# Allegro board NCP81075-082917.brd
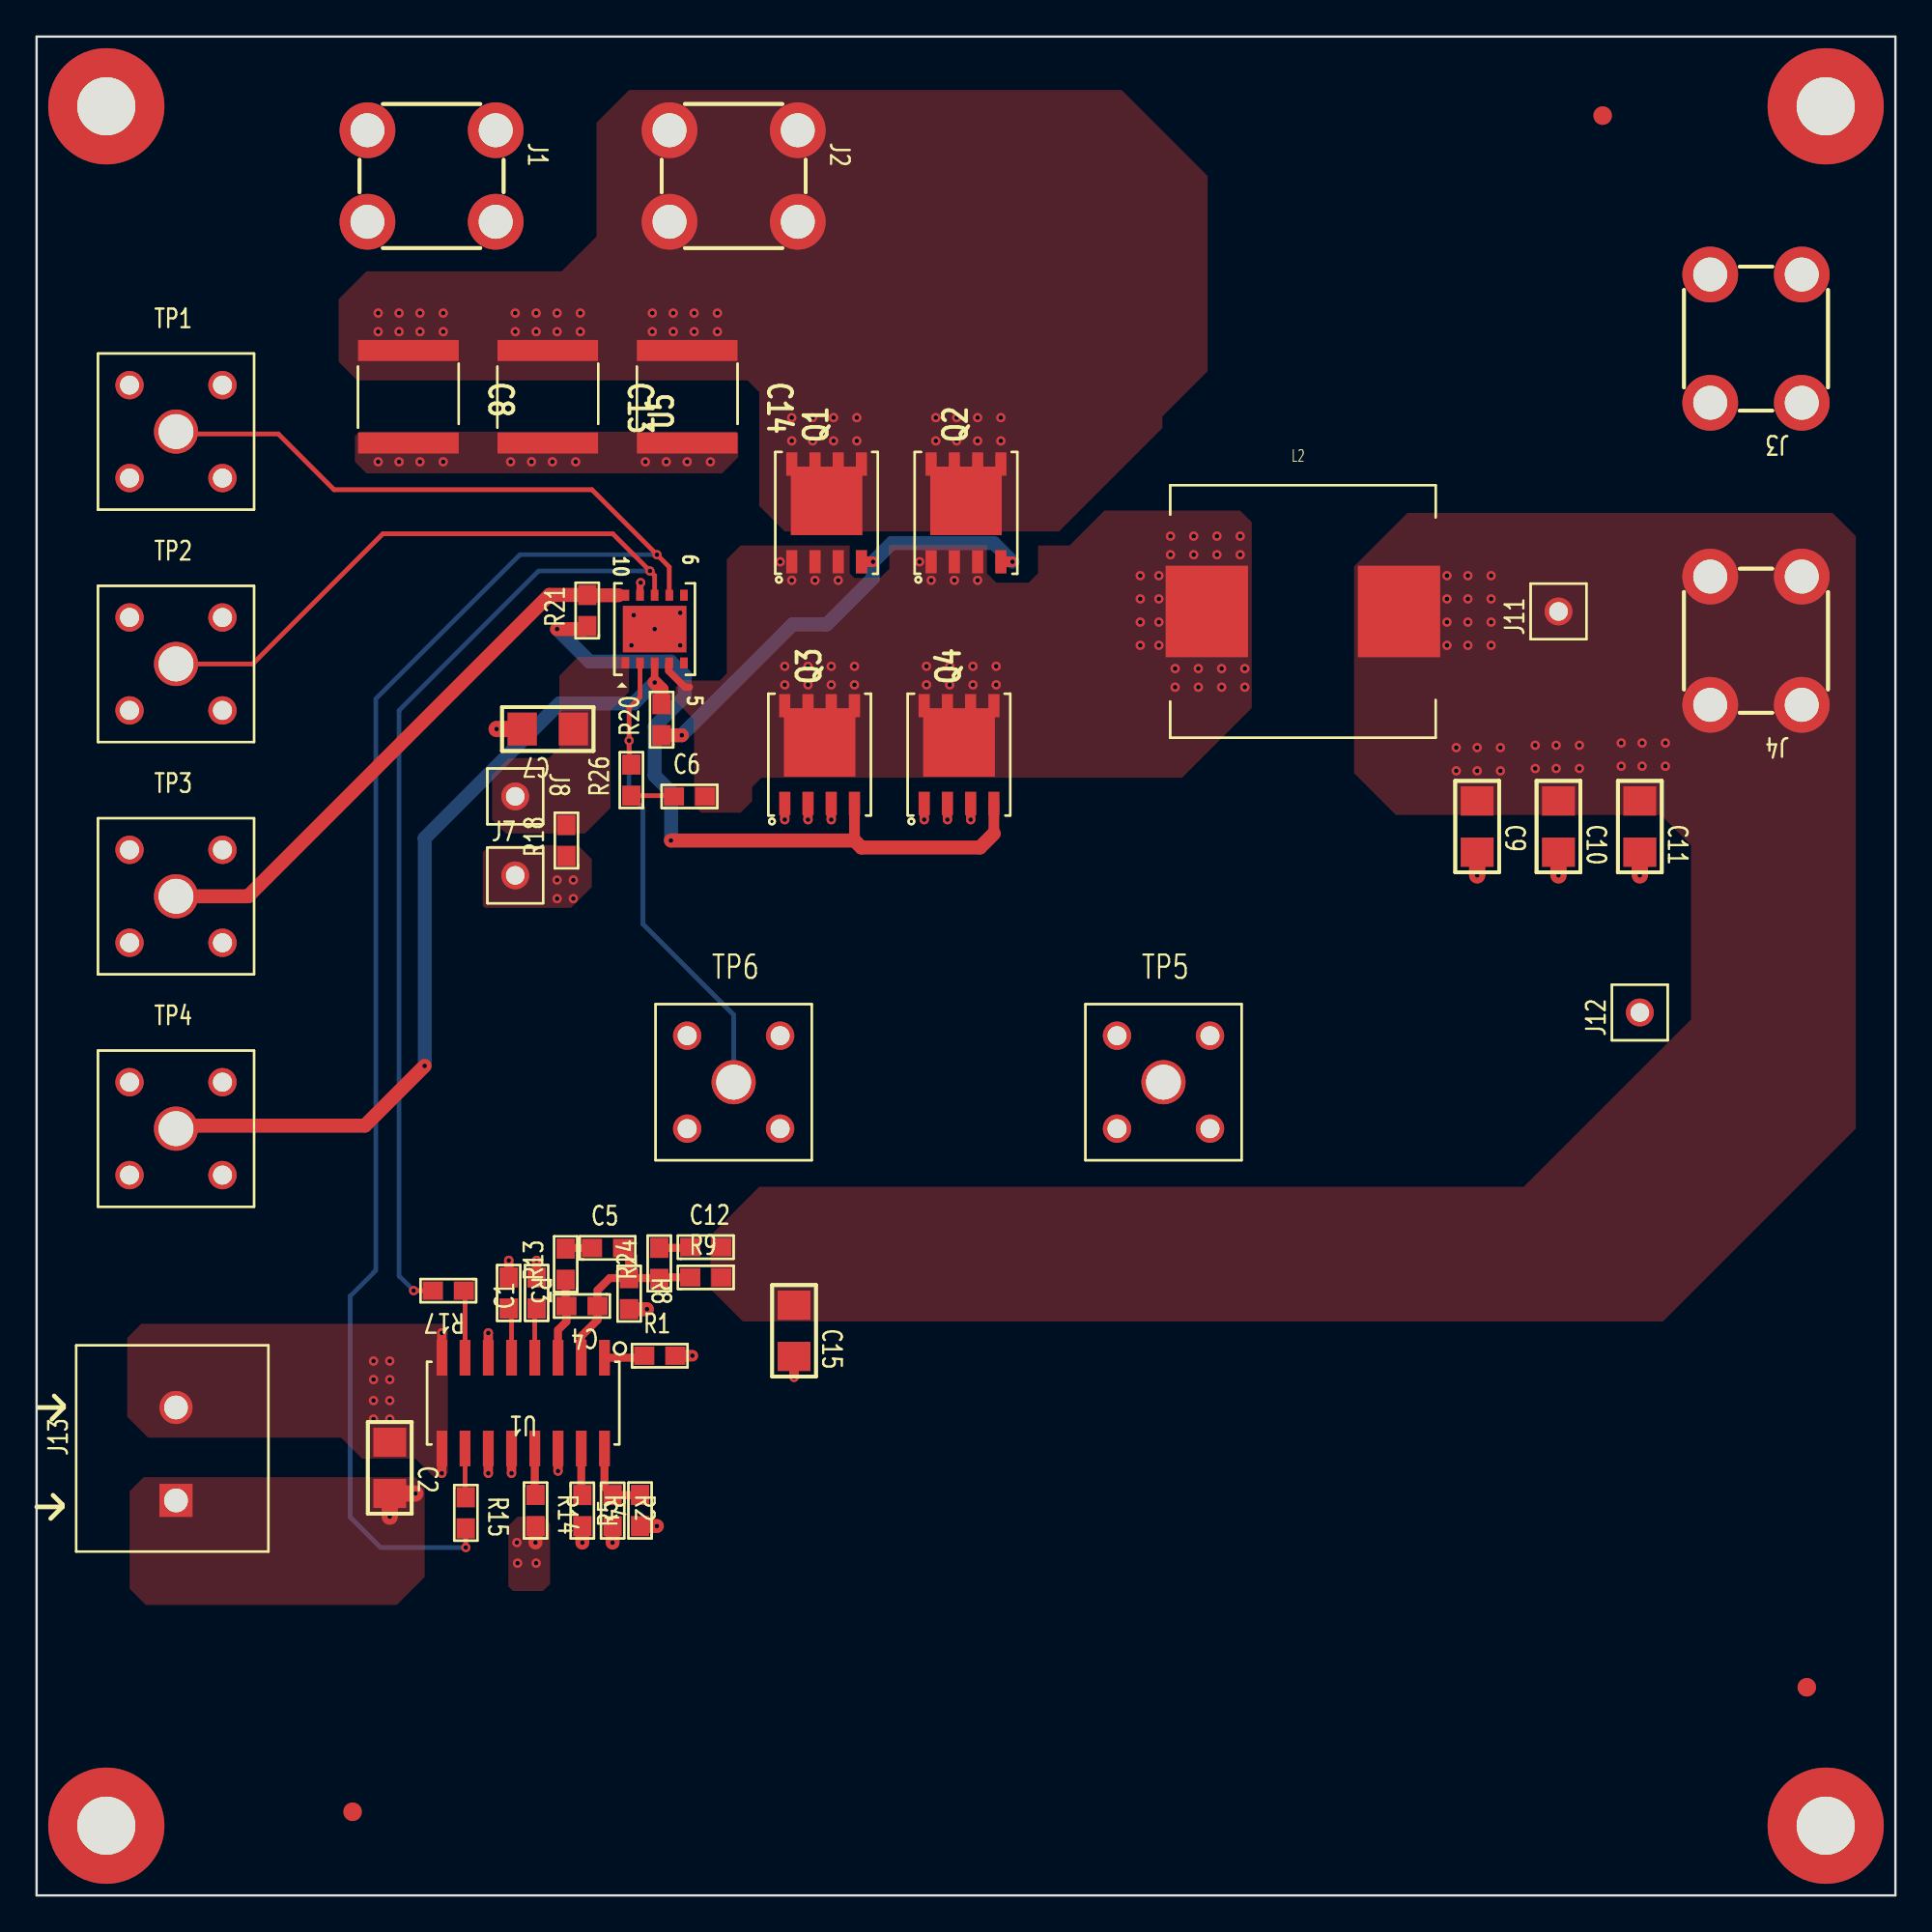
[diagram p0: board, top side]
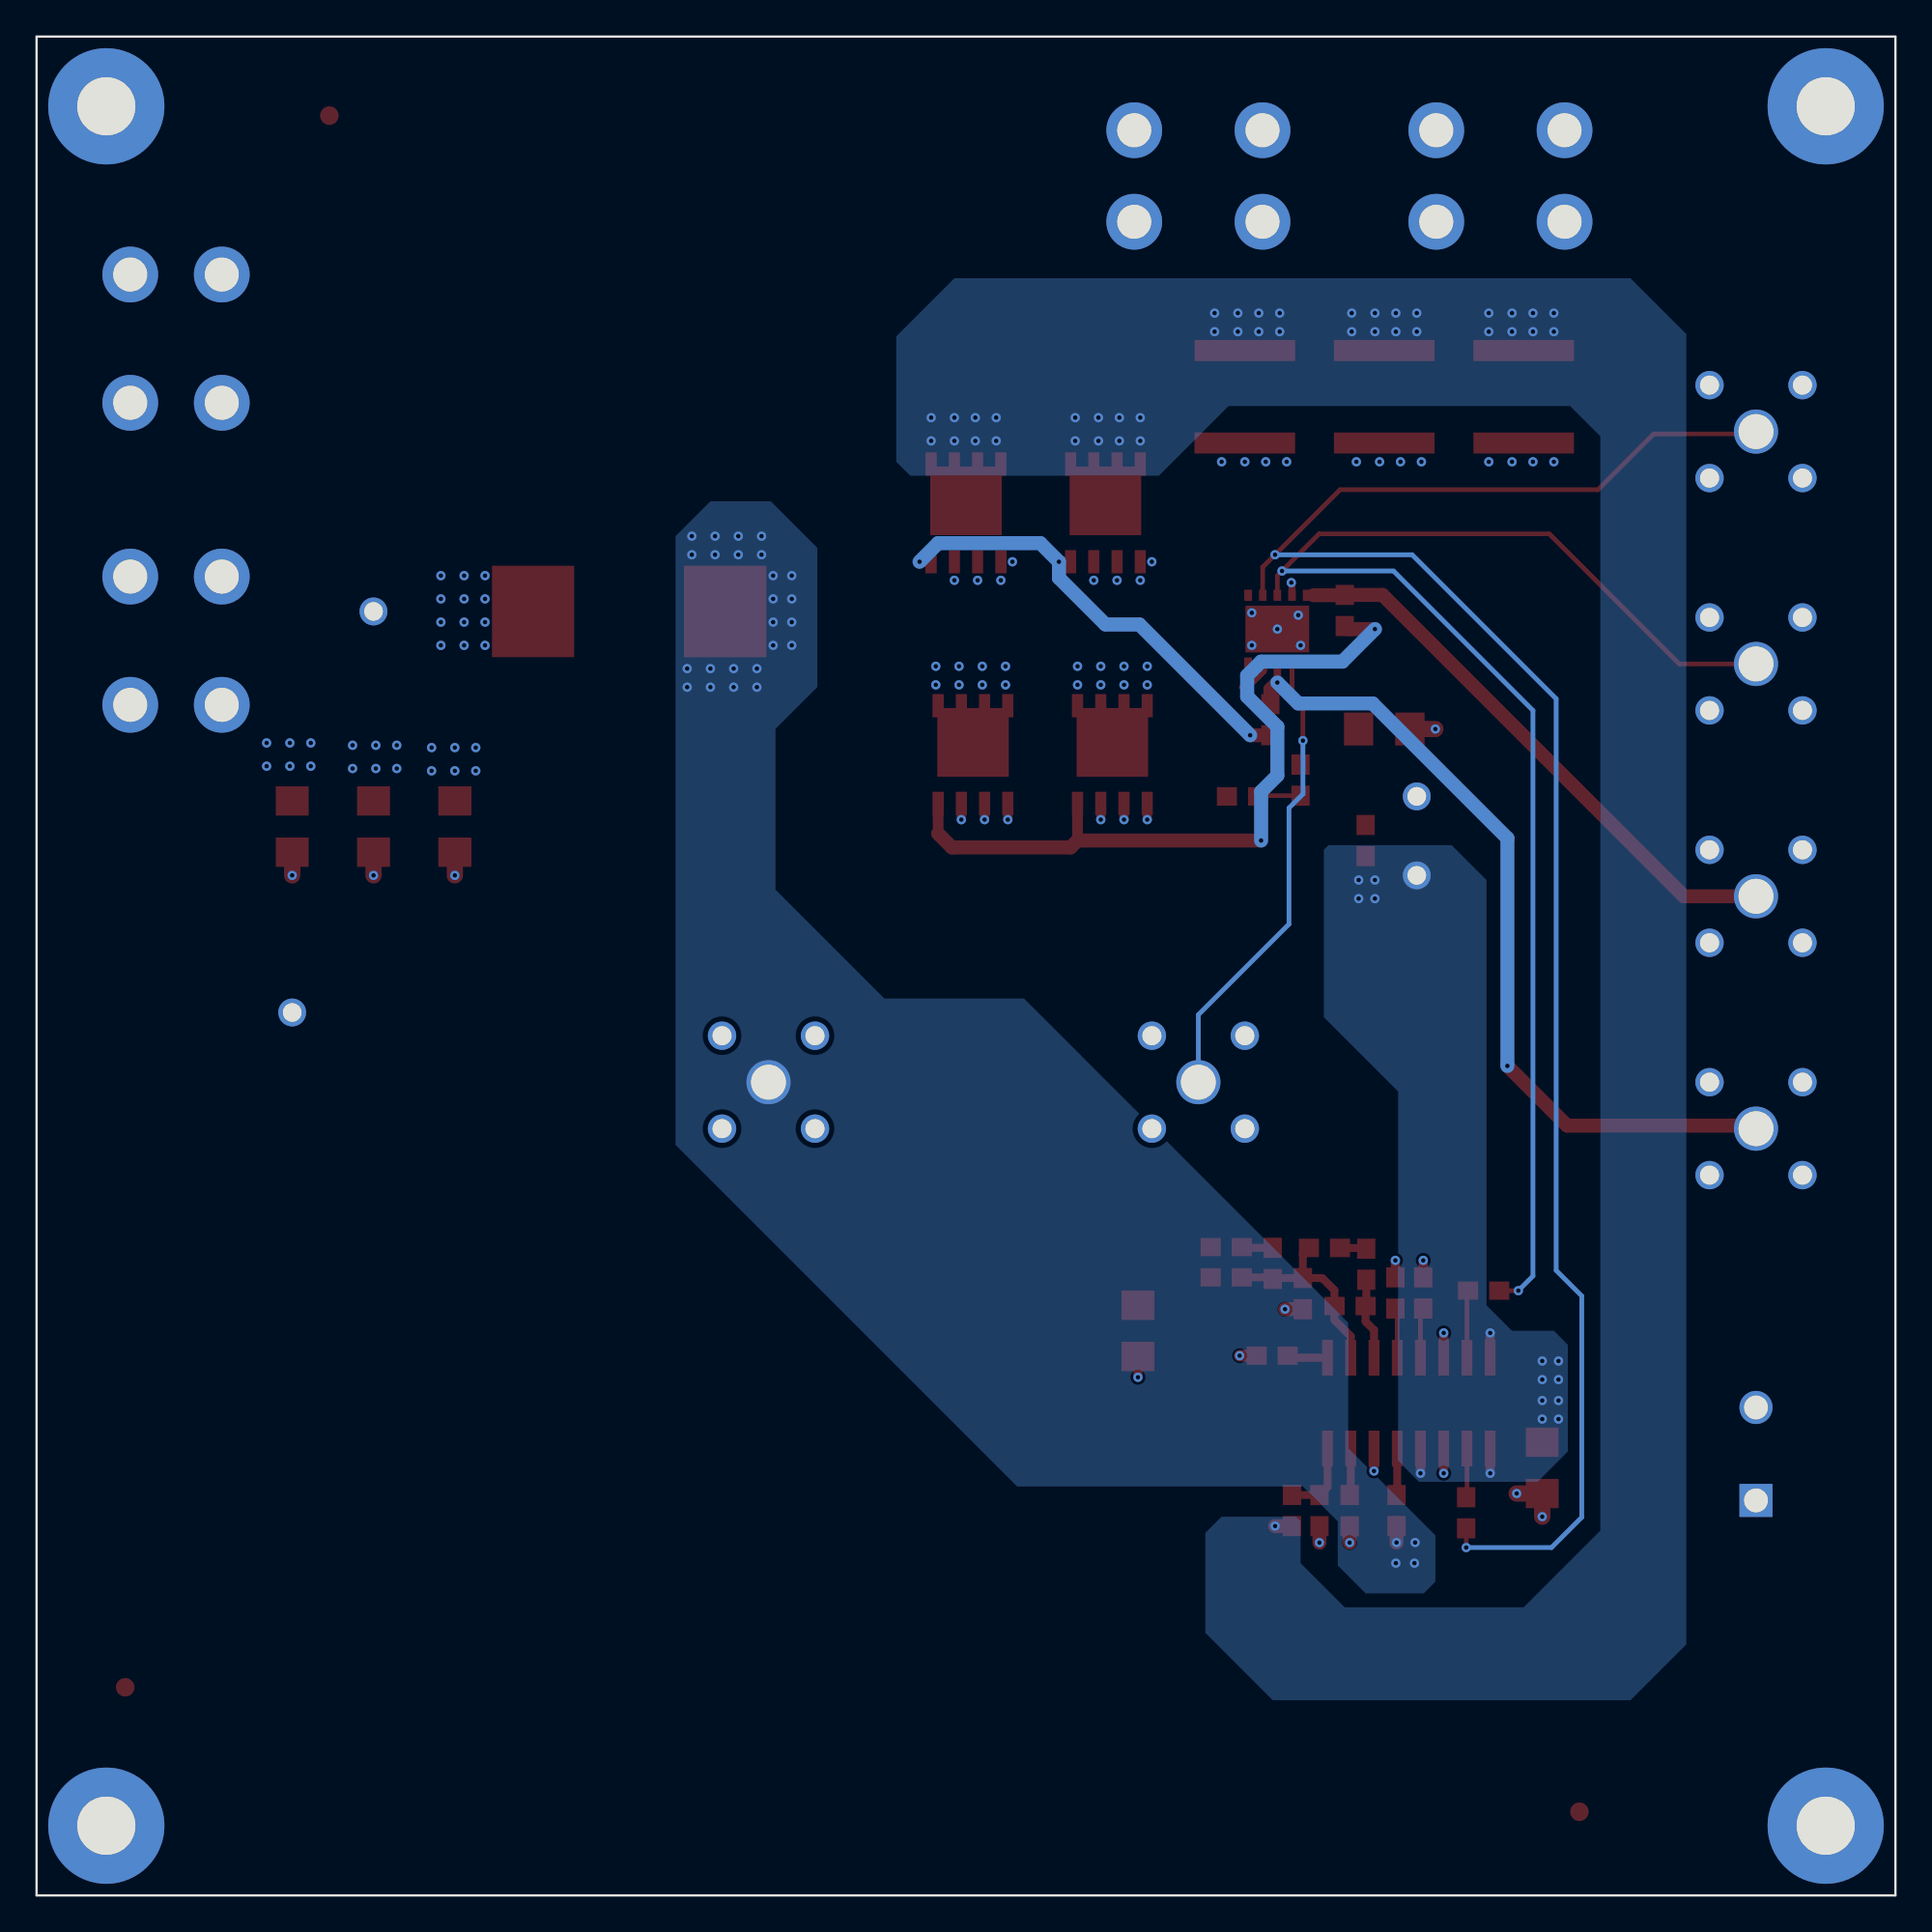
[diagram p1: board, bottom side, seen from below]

Outline 101.6 x 101.6 mm; copper layers: TOP, GND1#2, GND2#3, BOTTOM. Coordinates in mm from the lower left corner of the outline.
Outline path: 0,101.6 0,0 101.6,0 101.6,101.6 0,101.6

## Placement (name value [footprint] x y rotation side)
C1  220nF  [0603]  27.33 32.93 90 top
C2  4.7uF  [SMD1206]  19.3 23.37 270 top
C4  330pF  [0603]  29.81 32.21 180 top
C5  12nF  [0603]  31.21 35.39 0 top
C6  100nF  [0603]  35.69 60.07 0 top
C7  4.7uF  [SMD1206]  27.94 63.75 180 top
C8  10uF  [SMD2220]  20.32 81.92 270 top
C9  47uF  [SMD1206]  78.74 58.42 270 top
C10  47uF  [SMD1206]  83.19 58.42 270 top
C11  47uF  [SMD1206]  87.63 58.42 270 top
C12  1.8nF  [0603]  36.58 35.43 0 top
C13  10uF  [SMD2220]  27.94 81.92 270 top
C14  10uF  [SMD2220]  35.56 81.92 270 top
C15  47uF  [SMD1206]  41.4 30.86 270 top
J1  4PIN  [TRM4]  21.59 93.98 270 top
J2  4PIN  [TRM4]  38.1 93.98 270 top
J3  4PIN  [TRM4]  93.98 85.09 180 top
J4  4PIN  [TRM4]  93.98 68.58 180 top
J7  TP  [TRM1]  26.16 55.75 0 top
J8  TP  [TRM1]  26.16 60.07 270 top
J11  TP  [TRM1]  83.19 70.18 90 top
J12  TP  [TRM1]  87.63 48.26 90 top
J13  2PIN/TERM BLK  [TRM2]  7.62 24.13 90 top
L2  7443551181  [INDUCTOR]  69.22 70.18 0 top
NOREF  -  [unnamed]  3.81 3.81 0 top
NOREF#2  -  [unnamed]  96.76 11.38 0 top
NOREF#3  -  [#2]  0 0 0 top
NOREF#4  -  [unnamed]  97.79 3.81 0 top
NOREF#5  -  [#2]  0 0 0 top
NOREF#6  -  [unnamed]  85.6 97.28 0 top
NOREF#7  -  [#2]  3.81 97.79 0 top
NOREF#8  -  [unnamed]  3.81 97.79 0 top
NOREF#9  -  [unnamed]  17.27 4.57 0 top
NOREF#10  -  [#2]  101.6 0.13 90 top
NOREF#11  -  [#2]  0 101.6 0 top
NOREF#12  -  [unnamed]  97.79 97.79 0 top
Q1  FDMS86102LZ  [PQFN-8]  43.18 75.56 90 top
Q2  FDMS86102LZ  [PQFN-8]  50.8 75.56 90 top
Q3  FDMS86102LZ  [PQFN-8]  42.8 62.36 90 top
Q4  FDMS86102LZ  [PQFN-8]  50.42 62.36 90 top
R1  10K  [0603]  34.06 29.5 0 top
R2  DNP  [0603]  31.48 21.03 270 top
R3  10K  [0603]  25.81 32.93 270 top
R4  20K  [0603]  29.83 21.03 270 top
R5  100K  [0603]  32.98 21.04 90 top
R8  5.6k  [0603]  32.38 32.89 270 top
R9  16.9k  [0603]  36.58 33.78 0 top
R13  4.7K  [0603]  28.92 34.5 90 top
R14  10K  [0603]  27.27 21.04 270 top
R15  0  [0603]  23.46 20.91 270 top
R17  0  [0603]  22.5 33.06 180 top
R18  1  [0603]  28.96 57.66 90 top
R20  2.2  [0603]  34.16 64.26 90 top
R21  2.2  [0603]  30.1 70.23 90 top
R24  1.2K  [0603]  34.04 34.54 90 top
R26  2.2  [0603]  32.51 60.96 90 top
TP1  Probe Ground Tip  [SMA]  7.62 80.01 0 top
TP2  Probe Ground Tip  [SMA]  7.62 67.31 0 top
TP3  Probe Ground Tip  [SMA]  7.62 54.61 0 top
TP4  Probe Ground Tip  [SMA]  7.62 41.91 0 top
TP5  Probe Ground Tip  [SMA]  61.59 44.45 0 top
TP6  Probe Ground Tip  [SMA]  38.1 44.45 0 top
U1  NCP1034  [SOIC-16]  26.59 26.91 180 top
U5  NCP81075  [DFN8]  33.78 69.22 90 top
UNK*  -  [#2]  32 -36.07 0 top

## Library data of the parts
C1 = CAP_9
C2 = CAP_4
C4 = CAP_6
C5 C12 = CAP_7
C6 = CAP_11
C7 = CAP_10
C8 C13 C14 = CAP_12
C9 C11 C15 = CAP_14
C10 = CAP_15
J1 = Power_term_0
J2-J4 = Power_term
J7 J8 J11 J12 = TP_SQUARE
J13 = Term_Blk_2_0.2
L2 = INDUCTOR_0
Q1-Q4 = MTD10N05E_0
R1 = RES_19
R2 = RES_15
R3 = RES_17
R4 = RES_18
R5 = RES_14
R8 = RES_11
R9 R24 = RES_10
R13 = RES_12
R14 = RES_6
R15 = RES_20
R17 = RES_5
R18 = RES_13
R20 R21 R26 = RES_9
TP1-TP6 = BNC_0
U1 = COP245C_0
U5 = ADP3418_3

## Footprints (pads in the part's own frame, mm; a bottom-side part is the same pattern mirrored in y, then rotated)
0603
  rect 1.1x1 smd: 1(-0.85,0) 2(0.85,0)
DFN8
  rect 0.6x0.42 smd: 1(-1.85,1.6) 2(-1.85,0.8) 3(-1.85,0) 4(-1.85,-0.8) 5(-1.85,-1.6) 6(1.85,-1.6) 7(1.85,-0.8) 8(1.85,0) 9(1.85,0.8) 10(1.85,1.6)
  rect 2.55x3.48 smd: TAB(0,0)
INDUCTOR
  rect 4.5x5 smd: 1(-5.25,0) 2(5.25,0)
PQFN-8
  rect 1.27x0.61 smd: 1(-2.67,1.905) 2(-2.67,0.635) 3(-2.67,-0.635) 4(-2.67,-1.905)
  custom 1.105x1.105 smd: 5(1.045,0)
SMA
  round 2.413 hole 1.905: 1(0,0)
  round 1.549 hole 1.041: 2(2.54,-2.54) 3(2.54,2.54) 4(-2.54,2.54) 5(-2.54,-2.54)
SMD1206
  rect 1.6x1.8 smd: 1(-1.4,0) 2(1.4,0)
SMD2220
  rect 1.15x5.5 smd: 1(-2.53,0) 2(2.53,0)
SOIC-16
  rect 0.59x1.95 smd: 1(-4.445,-2.48) 2(-3.175,-2.48) 3(-1.905,-2.48) 4(-0.635,-2.48) 5(0.635,-2.48) 6(1.905,-2.48) 7(3.175,-2.48) 8(4.445,-2.48) 9(4.445,2.48) 10(3.175,2.48) 11(1.905,2.48) 12(0.635,2.48) 13(-0.635,2.48) 14(-1.905,2.48) 15(-3.175,2.48) 16(-4.445,2.48)
TRM1
  round 1.524 hole 1.016: 1(0,0)
TRM2
  rect 1.808x1.808 hole 1.3: 1(-2.54,0)
  round 1.808 hole 1.3: 2(2.54,0)
TRM4
  round 3.048 hole 1.854: 1(-2.502,3.505) 2(2.502,3.505) 3(-2.502,-3.505) 4(2.502,-3.505)
unnamed
  round 6.35 hole 3.175 unplated: (0,0)

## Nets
12V: C2.1 J7.1 J13.2 R18.1 U1.8(DRVVCC) U1.9(VB) U1.12(VCC)
GND: C1.2 C2.2 C7.2 C8.2 C9.2 C10.2 C11.2 C13.2 C14.2 C15.2 J1.1 J1.2 J1.3 J1.4 J3.1 J3.2 J3.3 J3.4 J12.1 J13.1 Q3.1(S1) Q3.2(S2) Q3.3(S3) Q4.1(S1) Q4.2(S2) Q4.3(S3) R1.2 R2.2 R3.1 R4.2 R8.2 TP1.2(SHIELD2) TP1.3(SHIELD3) TP1.4(SHIELD4) TP1.5(SHIELD5) TP2.2(SHIELD2) TP2.3(SHIELD3) TP2.4(SHIELD4) TP2.5(SHIELD5) TP3.2(SHIELD2) TP3.3(SHIELD3) TP3.4(SHIELD4) TP3.5(SHIELD5) TP4.2(SHIELD2) TP4.3(SHIELD3) TP4.4(SHIELD4) TP4.5(SHIELD5) TP5.2(SHIELD2) TP5.3(SHIELD3) TP5.4(SHIELD4) TP5.5(SHIELD5) TP6.2(SHIELD2) TP6.3(SHIELD3) TP6.4(SHIELD4) TP6.5(SHIELD5) U1.6(PGND) U1.11(VS) U1.14(GND) U5.9(VSS) U5.TAB(PAD)
VIN: C8.1 C13.1 C14.1 J2.1 J2.2 J2.3 J2.4 Q1.5(D1) Q2.5(D1) R5.1
HI: R15.2 TP1.1(CENTER) U5.7(HI)
HS: C6.2 L2.1 Q1.1(S1) Q1.2(S2) Q1.3(S3) Q2.1(S1) Q2.2(S2) Q2.3(S3) Q3.5(D1) Q4.5(D1) R14.2 TP5.1(CENTER) U5.4(HS)
LI: R17.2 TP2.1(CENTER) U5.8(LI)
VOUT: C9.1 C10.1 C11.1 C12.2 C15.1 J4.1 J4.2 J4.3 J4.4 J11.1 L2.2 R9.2
N00462: R1.1 U1.1(OCSET)
N00471: R4.1 U1.15(RT)
N00478: R2.1 R5.2 U1.16(UVLO)
N00520: C1.1 U1.4(SS/SD)
N00818: R3.2 U1.5(SYNC)
N02448: C4.2 R13.1 U1.3(COMP)
N02502: C4.1 C5.2 R8.1 R9.1 R24.1 U1.2(FB)
N03255: R17.1 U1.7(LDRV)
N03294: R15.1 U1.10(HDRV)
N03349: R14.1 U1.13(OCIN)
N05672: C7.1 J8.1 R18.2 U5.1(VDD)
N16019: R20.2 TP4.1(CENTER) U5.3(HO)
N16711: R21.2 TP3.1(CENTER) U5.10(LO)
N22591: Q1.4(GATE) Q2.4(GATE) R20.1
N23756: Q3.4(GATE) Q4.4(GATE) R21.1
N056450: C6.1 R26.1
N88056: C5.1 R13.2
N102548: R26.2 TP6.1(CENTER) U5.2(HB)
N912481: C12.1 R24.2

Pads without a net: U5 5 6

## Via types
v1: diameter 0.508, hole 0.254, TOP to BOTTOM, 190 vias

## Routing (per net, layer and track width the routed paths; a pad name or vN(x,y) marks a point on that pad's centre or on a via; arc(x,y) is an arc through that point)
12V: length 4.1
  TOP w0.508: U1.12 v1(25.96,23.07) ; U1.9 v1(22.15,23.07) ; U1.8 v1(22.15,30.74)
  vias: v1(18.41,29.21) v1(18.41,28.19) v1(18.41,27.05) v1(18.41,26.04) v1(19.3,29.21) v1(19.3,28.19) v1(19.3,27.05) v1(19.3,26.04) v1(28.45,55.5) v1(28.45,54.48) v1(29.34,55.5) v1(29.34,54.48)
GND: length 24.5
  TOP w0.381: U5.9 32.98,71.72 v1(33.02,71.75)
  TOP w0.508: C15.2 v1(41.4,28.32) ; Q4.2 v1(49.78,58.8) ; U1.11 v1(24.69,23.07) ; R3.1 v1(25.81,34.71) ; C1.2 v1(27.33,34.71) ; U1.14 v1(28.5,23.2) ; Q4.1 v1(48.51,58.8) ; Q3.1 v1(40.89,58.8) ; Q4.3 v1(51.05,58.8) ; Q3.3 v1(43.43,58.8) ; Q3.2 v1(42.16,58.8) ; U1.6 v1(24.69,30.74)
  TOP w0.635: R1.2 v1(35.84,29.5)
  TOP w0.762: R4.2 v1(29.83,19.28) ; R8.2 v1(33.36,32.04) ; R2.2 v1(31.48,19.28)
  TOP w0.889: v1(20.7,21.97) C2.2 v1(19.3,20.7) ; C11.2 v1(87.63,55.75) ; C7.2 v1(25.15,63.75) ; C10.2 v1(83.19,55.75) ; C9.2 v1(78.74,55.75)
  vias: v1(18.67,78.36) v1(19.81,78.36) v1(20.95,78.36) v1(22.23,78.36) v1(25.91,78.36) v1(27.05,78.36) v1(28.19,78.36) v1(29.46,78.36) v1(32.51,68.33) v1(32.64,69.98) v1(33.27,78.36) v1(33.78,69.22) v1(34.42,78.36) v1(35.18,70.1) v1(35.18,68.33) v1(35.56,78.36) v1(36.83,78.36)
VIN: length 0.9
  TOP w0.762: R5.1 v1(33.9,20.19)
  vias: v1(18.67,86.49) v1(18.67,85.47) v1(19.81,86.49) v1(19.81,85.47) v1(20.95,86.49) v1(20.95,85.47) v1(22.23,86.49) v1(22.23,85.47) v1(26.16,86.49) v1(26.16,85.47) v1(27.3,86.49) v1(27.3,85.47) v1(28.45,86.49) v1(28.45,85.47) v1(29.72,86.49) v1(29.72,85.47) v1(33.66,86.49) v1(33.66,85.47) v1(34.8,86.49) v1(34.8,85.47) v1(35.94,86.49) v1(35.94,85.47) v1(37.21,86.49) v1(37.21,85.47) v1(41.27,80.77) v1(41.27,79.5) v1(42.42,80.77) v1(42.42,79.5) v1(43.56,80.77) v1(43.56,79.5) v1(44.83,80.77) v1(44.83,79.5) v1(49.15,80.77) v1(49.15,79.5) v1(50.29,80.77) v1(50.29,79.5) v1(51.44,80.77) v1(51.44,79.5) v1(52.7,80.77) v1(52.7,79.5)
HI: length 103.6
  TOP w0.254: TP1.1 7.75,79.88 13.21,79.88 16.26,76.83 30.35,76.83 v1(33.91,73.28) 34.58,72.61 U5.7 ; R15.2 v1(23.46,19.01)
  BOTTOM w0.254: v1(23.46,19.01) 18.8,19.01 17.14,20.67 17.14,32.77 18.54,34.16 18.54,65.41 26.42,73.28 v1(33.91,73.28)
HS: length 2.9
  TOP w0.381: 35.69,66.04 35.43,66.04 34.54,66.93 34.54,67.33 U5.4
  TOP w0.762: R14.2 v1(27.27,19.29)
  vias: v1(26.25,19.29) v1(26.29,18.16) v1(27.3,18.16) v1(40.64,72.9) v1(40.89,67.18) v1(40.89,66.17) v1(41.27,71.88) v1(42.16,67.18) v1(42.16,66.17) v1(42.55,71.88) v1(43.43,67.18) v1(43.43,66.17) v1(43.81,71.88) v1(44.7,67.18) v1(44.7,66.17) v1(48.26,72.9) v1(48.64,67.18) v1(48.64,66.17) v1(48.9,71.88) v1(49.91,67.18) v1(49.91,66.17) v1(50.16,71.88) v1(51.18,67.18) v1(51.18,66.17) v1(51.44,71.88) v1(52.45,67.18) v1(52.45,66.17) v1(60.33,72.14) v1(60.33,70.87) v1(60.33,69.6) v1(60.33,68.33) v1(61.34,72.14) v1(61.34,70.87) v1(61.34,69.6) v1(61.34,68.33) v1(61.98,74.3) v1(61.98,73.28) v1(62.23,67.06) v1(62.23,66.04) v1(63.25,74.3) v1(63.25,73.28) v1(63.5,67.06) v1(63.5,66.04) v1(64.52,74.3) v1(64.52,73.28) v1(64.77,67.06) v1(64.77,66.04) v1(65.79,74.3) v1(65.79,73.28) v1(66.04,67.06) v1(66.04,66.04)
LI: length 81.1
  TOP w0.254: TP2.1 11.81,67.31 18.92,74.42 31.5,74.42 v1(33.53,72.39) 33.78,72.14 U5.8 ; R17.2 v1(20.61,33.06)
  BOTTOM w0.254: v1(33.53,72.39) 27.43,72.39 19.81,64.77 19.81,33.85 v1(20.61,33.06)
VOUT:
  vias: v1(77.09,72.14) v1(77.09,70.87) v1(77.09,69.6) v1(77.09,68.33) v1(77.6,62.74) v1(77.6,61.47) v1(78.23,72.14) v1(78.23,70.87) v1(78.23,69.6) v1(78.23,68.33) v1(78.74,62.74) v1(78.74,61.47) v1(79.5,72.14) v1(79.5,70.87) v1(79.5,69.6) v1(79.5,68.33) v1(80.01,62.74) v1(80.01,61.47) v1(81.92,62.87) v1(81.92,61.59) v1(83.06,62.87) v1(83.06,61.59) v1(84.33,62.87) v1(84.33,61.59) v1(86.61,62.99) v1(86.61,61.72) v1(87.76,62.99) v1(87.76,61.72) v1(89.03,62.99) v1(89.03,61.72)
N00462: length 2.2
  TOP w0.432: R1.1 33.1,29.39 U1.1
N00471: length 2.6
  TOP w0.432: R4.1 29.77,21.94 U1.15
N00478: length 4.2
  TOP w0.432: U1.16 31.04,22.32 R2.1 32.98,21.88 R5.2
N00520: length 2.7
  TOP w0.254: C1.1 27.23,31.98 U1.4
N00818: length 2.8
  TOP w0.254: U1.5 25.96,31.93 R3.2
N02448: length 4.5
  TOP w0.432: R13.1 28.92,32.25 C4.2 28.96,31.36 28.5,30.9 U1.3
N02502: length 11.2
  TOP w0.432: C5.2 32.38,35.06 R8.1 ; R8.1 31.33,33.74 30.66,33.07 C4.1 30.66,31.45 29.77,30.56 U1.2 ; R8.1 33.99,33.74 R24.1 34.12,33.78 R9.1
N03255: length 3.7
  TOP w0.254: U1.7 23.42,32.99 R17.1
N03294: length 2.7
  TOP w0.254: R15.1 23.42,21.8 U1.10
N03349: length 2.6
  TOP w0.432: U1.13 27.23,21.93 R14.1
N16019: length 46
  TOP w0.406: v1(33.78,66.29) U5.3
  TOP w0.762: v1(21.21,45.34) 17.95,42.08 7.79,42.08 TP4.1 ; v1(33.78,66.29) 34.16,65.91 R20.2
  BOTTOM w0.762: v1(33.78,66.29) 32.64,65.15 28.57,65.15 21.21,57.78 v1(21.21,45.34)
N16711: length 31.4
  TOP w0.254: 31.8,71.07 U5.10
  TOP w0.762: TP3.1 11.56,54.61 28.03,71.08 R21.2 30.11,71.07 31.8,71.07
N22591: length 25.7
  TOP w0.584: Q1.4 v1(45.72,72.9) ; Q2.4 v1(53.34,72.9)
  TOP w0.762: R20.1 v1(35.27,63.41)
  BOTTOM w0.762: v1(35.27,63.41) 41.32,69.47 43.18,69.47 45.72,72.01 v1(45.72,72.9) 46.74,73.91 52.32,73.91 v1(53.34,72.9)
N23756: length 41.6
  TOP w0.584: Q4.4 52.32,58.04 ; 44.7,57.66 Q3.4
  TOP w0.762: R21.1 29.93,69.22 v1(28.45,69.22) ; 52.32,58.04 51.56,57.28 45.09,57.28 44.7,57.66 v1(34.67,57.66)
  BOTTOM w0.762: v1(28.45,69.22) 30.23,67.44 34.67,67.44 35.43,66.67 35.43,65.53 33.78,63.88 33.78,61.21 34.67,60.33 v1(34.67,57.66)
N056450: length 2.3
  TOP w0.254: R26.1 34.8,60.11 C6.1
N88056: length 1.5
  TOP w0.432: C5.1 28.96,35.39 R13.2
N102548: length 26.8
  TOP w0.254: R26.2 32.38,62.57 v1(32.38,63.12) 32.38,64.9 32.98,65.49 U5.2
  BOTTOM w0.254: TP6.1 38.1,48.13 33.15,53.09 33.15,59.44 32.38,60.2 v1(32.38,63.12)
N912481: length 1.7
  TOP w0.432: R24.2 35.69,35.39 C12.1

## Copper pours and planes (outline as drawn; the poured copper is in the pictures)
12V on TOP: 22.48,23.11 22.48,30.99 22.23,31.24 5.71,31.24 4.95,30.48 4.95,26.16 6.1,25.02 16.64,25.02 17.78,23.88 20.7,23.88 21.72,22.86 22.23,22.86
12V on TOP: 29.59,57.4 24.77,57.4 24.38,57.02 24.38,54.1 24.51,53.98 29.21,53.98 30.35,55.12 30.35,56.64
12V on BOTTOM: 30.99,57.4 24.26,57.4 22.35,55.5 22.35,32.26 20.95,30.86 18.67,30.86 17.91,30.1 17.91,24.26 19.56,22.61 26.04,22.61 27.18,23.75 27.18,43.94 31.24,48.01 31.24,57.15
GND on TOP: 20.7,22.86 5.84,22.86 5.08,22.1 5.08,16.76 5.97,15.88 19.68,15.88 21.21,17.4 21.21,22.35
GND on TOP: 38.23,80.01 17.65,80.01 17.4,79.76 17.4,78.36 18.03,77.72 37.47,77.72 38.35,78.61 38.35,79.88
GND on GND1#2, GND2#3: 0.51,0.51 0.51,101.09 101.09,101.09 101.09,0.51 ; 4 cut-outs
VIN on TOP: 39.5,82.17 38.86,82.8 17.53,82.8 16.51,83.82 16.51,87.25 18.03,88.77 28.7,88.77 30.61,90.68 30.61,96.9 32.38,98.68 59.31,98.68 64.01,93.98 64.01,83.31 61.53,80.84 61.53,80.2 55.88,74.55 40.89,74.55 39.5,75.95
VIN on BOTTOM: 14.48,88.39 11.43,85.34 11.43,13.72 14.48,10.67 34.04,10.67 37.72,14.35 37.72,19.81 36.83,20.7 32.77,20.7 32.51,20.45 32.51,18.16 30.1,15.75 20.32,15.75 16.13,19.94 16.13,79.76 17.78,81.41 36.45,81.41 40.26,77.6 53.85,77.6 54.61,78.36 54.61,85.22 51.44,88.39
HS on TOP: 37.72,73.03 37.72,66.78 37.34,66.4 35.29,66.4 34.93,66.04 34.93,65.28 35.94,64.26 35.94,59.56 36.32,59.18 38.48,59.18 39.12,59.82 39.12,60.58 39.62,61.09 62.61,61.09 66.42,64.9 66.42,75.06 65.79,75.69 58.37,75.69 56.46,73.79 54.74,73.79 54.74,72.26 54.23,71.75 52.45,71.75 51.94,72.26 51.94,73.79 46.61,73.79 46.61,72.52 46.1,72.01 44.7,72.01 44.45,72.26 44.45,73.79 38.48,73.79
HS on TOP: 27.69,20.7 26.29,20.7 25.78,20.19 25.78,16.89 26.04,16.64 27.69,16.64 28.07,17.02 28.07,20.32
HS on BOTTOM: 61.47,76.2 64.77,76.2 66.67,74.3 66.67,41.02 65.79,40.13 48.01,22.35 32.38,22.35 30.48,20.45 30.48,18.03 28.96,16.51 25.78,16.51 25.15,17.14 25.15,19.68 29.91,24.45 29.91,31.31 42.32,43.72 42.32,43.72 47.63,49.02 55.26,49.02 61.21,54.97 61.21,63.75 58.93,66.04 58.93,73.66
VOUT on TOP: 98.17,75.56 74.93,75.56 72.01,72.64 72.01,61.34 74.3,59.05 88.77,59.05 90.42,57.4 90.42,47.88 81.28,38.73 39.5,38.73 36.83,36.07 36.83,33.15 38.61,31.37 88.9,31.37 99.44,41.91 99.44,74.3
N05672 on TOP: 28.57,66.67 28.57,62.74 28,62.17 25.84,62.17 24.89,61.21 24.89,58.8 25.65,58.04 29.97,58.04 31.37,59.44 31.37,64.77 32.38,65.79 32.38,67.69 29.59,67.69

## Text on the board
BOTTOM: BOTTOM
Board Geometry/Soldermask Bottom: SOLDERMASK_BOTTOM
Ref Des/Assembly Top: HI | LI | LO | HO | 12V | GND | HB | VIN | HS | NCP81075 CLOSED LOOP BUCK REV.2 | VOUT
Board Geometry/Soldermask Top: SOLDERMASK_TOP
GND1#2: GND1#2
GND2#3: GND2#3
User.16: TOP
User.20: ASSEMBLY_TOP
User.25: PASTEMASK_TOP
User.32: SILK_TOP
User.33: DRAWN: | CHECKED: | QUALITY CONTROL: | RELEASED: | DATED: | AUG 2017 | TITLE: | SCALE: | CODE: | NCP81075 CLOSED LOOP BUCK | SIZE: | LTR | DRAWING NO: | ATP-17-0026 | ECO NO: | REVISION RECORD | SHEET:     OF | APPROVED: | REV: | DATE: | 2 | (COPPER+PLATING) | 0.70 | 1.4 | LAYER STACKUP DETAIL | 4 LAYER BOARD | SCALE: NONE | SOLDERMASK (BOTTOM) | SILKSCREEN (BOTTOM) | SOLDERMASK (TOP) | SILKSCREEN (TOP) | L4_BOTTOM | L2_GND-1 | L3_GND-2 | L1_TOP | 16.FOLLOW GERBERS FOR EXACT BOARD OUTLINE | 17. DRILL NEED TO BE NON-CONDUCTIVE FILL AND SHOULD BE FLAT AND SMOOTH AND PLATED OVER ON TOP AND BOTTOM SIDE | 14.REMOVE NONFUNCTIONAL PADS IN ALL INNER LAYERS. | 15.SOLDERMASK AND SILKSCREEN LEGENDS SHALL NOT INFRINGE ON ANY EXPOSED LAND AREAS. | 1. BOARD DIMENSIONS ARE IN INCHES[MM]. | 2. MATERIAL: FR4, 4 LAYER BOARD | 3. PLATING: IMMERSION GOLD. | 5.MINIMUM PLATING IN ALL THE THROUGH HOLE SHALL BE 0.001 INCH Cu. | 6.ALL HOLES ARE PLATED THROUGH UNLESS OTHERWISE SPECIFIED. | 8. SOLDER MASK BOTH SIDE WITH GREEN LIQUID PHOTO IMAGABLE | 9. SILKSCREEN BOTH SIDE "WHITE EPOXY" OVER SOLDER MASK | 10. WARP AND TWIST SHOULD NOT EXCEED 0.007 INCHES PER INCH IN ANY DIRECTION | 11.ANY CHANGES MADE BY THE PCB FABRICATOR TO THE FILM OR THE GERBER FILES MUST BE APPROVED | 12.NO VENDOR LOGO OR NAME ON THE BOARD. | 13.DEBURR ALL SHARP EDGES | 4. BOARD THICKNESS:.062" +/- .006" TOL. | 7. HOLE SIZE ARE FINISHED SIZE. | 18. BOARD MUST BE ROHS COMPLAINT | NOTES: (UNLESS OTHERWISE SPECIFIED)
User.37: FAB | BOARD DIMENSIONS ARE IN MILS(MM) | 22. CLIP SILKSCREEEN ON NO MASK AREA. | 23. MASK OPENING SHOULD BE AS LIKE GERBER FILE,DON'T DO ANY GANG MASK OPENING | 21. PLATED PADS ON TOP AND BOTTOM MUST BE SAME HEIGHT AS CONDUCTOR PAD AND TRACE | 24. ARTWORKS SHOULD NOT BE CHANGED WITHOUT PRIOR APPROVAL | 20. FOR LAYER BUILD UP SEE STACK UP DETAIL. | 19. FABRICATE BOARD PER IPC-A-600G
User.38: BOARD OUTLINE
User.39: INSTALL AS WIRE | FACING OUT SIDE.
User.45: FIGURE | SIZE | 10.0 | 40.0 | 41.0 | 51.181 | 73.0 | 75.0 | 125.0 | DRILL CHART: TOP to BOTTOM | ALL UNITS ARE IN MILS | TOLERANCE | +3.0/-10.0 | +3.0/-3.0 | +3.0/-0.0 | +2.0/-2.0 | PLATED | NON-PLATED | QTY | 190 | 4 | 24 | 2 | 16 | 6
